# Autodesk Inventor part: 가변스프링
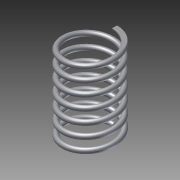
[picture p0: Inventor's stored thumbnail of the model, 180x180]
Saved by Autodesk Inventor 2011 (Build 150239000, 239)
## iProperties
Created: 2014-12
Part Number: 가변스프링
Document SubType Name: Modeling
Designer: user
Density: 1 g/cm^3
Mass: 20.4935 g
Surface Area: 165.64 cm^2
Volume: 20.4935 cm^3
Author: user
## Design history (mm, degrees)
sketch "스케치2"
  geometry: L1 (0, 0)-(24, 0); L2 (24, 0)-(24, 84.25); L3 (24, 84.25)-(0, 84.25); L4 (0, 84.25)-(0, 0); C1 r 2.5 at (24, 0)
  constraints: 8 end point, 2 parallel, 1 centre point, 1 coincident, 1 horizontal, 1 perpendicular
  dimensions: "d0" = 5 diameter of C1; "d1" = 48 diameter of L2 L4; "d2" = 84.25 distance between parallel lines of L1 L3 (derived)
feature "코일1" pitch "d3" = 10; turns "d5" = 7; dims "d4" = 84.25 (= d2), "d6" = 0, angle "d7" = 90 deg, angle "d8" = 90 deg, "d9" = 0, "d10" = 0
node "작업 평면1"
feature "분할1"
feature "분할2"
node "솔리드1"
other parameters: "d11" = 84.25
